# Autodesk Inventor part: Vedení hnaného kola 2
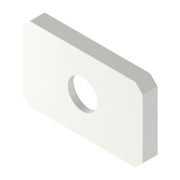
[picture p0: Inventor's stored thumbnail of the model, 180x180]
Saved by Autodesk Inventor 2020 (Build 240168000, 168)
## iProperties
Created: 2025-03
Part Number: Vedení hnaného kola 2
Material: Ocel
Document SubType Name: Modeling
Designer: doma
Density: 7.85 g/cm^3
Appearance: Ocel
Mass: 132.762 g
Surface Area: 69.1695 cm^2
Volume: 16.9123 cm^3
Author: doma
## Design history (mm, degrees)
sketch "Náčrt1"
  geometry: C1 r 37.5 at (0, 0); C2 r 17.5 at (0, 0)
  constraints: 2 centre point, 1 coincident
  dimensions: "d3" = 75 diameter of C1; "d4" = 35 diameter of C2
extrude "Vysunutí1" new body sketch "Náčrt1" distance "d7" = 8; taper "d8" = 0 deg
sketch "Náčrt2"
  geometry: L1 (-28.5, -20)-(28.5, -20); L2 (32.5, -16)-(32.5, 16); L3 (28.5, 20)-(-28.5, 20); L4 (-32.5, 16)-(-32.5, -16); L5 (-32.5, -20)-(32.5, 20); L6 (32.5, -20)-(-32.5, 20); L7 (-80.934, -49.806)-(80.934, -49.806); L8 (80.934, -49.806)-(80.934, 49.806); L9 (80.934, 49.806)-(-80.934, 49.806); L10 (-80.934, 49.806)-(-80.934, -49.806); L11 (-80.934, -49.806)-(80.934, 49.806); L12 (80.934, -49.806)-(-80.934, 49.806); L13 (-32.5, 16)-(-28.5, 20); L14 (32.5, 16)-(28.5, 20); L15 (28.5, -20)-(32.5, -16); L16 (-32.5, -16)-(-28.5, -20); 1 further point
  constraints: 32 end point, 8 point on line, 4 midpoint, 4 parallel, 2 horizontal, 2 perpendicular
  dimensions: "d9" = 65 distance of L6.end L5.end; "d10" = 40 distance of L5.end L6.start; "d13" = 4 distance of L4.start L6.end; "d14" = 4 distance of L3.end L6.end (= d13); "d15" = 4 distance of L2.end L5.end (= d13); "d16" = 4 distance of L3.start L5.end (= d15); "d17" = 4 distance of L1.end L6.start (= d13); "d18" = 4 distance of L2.start L6.start (= d17); "d19" = 4 distance of L4.end L5.start (= d13); "d20" = 4 distance of L1.start L5.start (= d19)
extrude "Vysunutí2" cut sketch "Náčrt2" distance "d11" = 8; taper "d12" = 0 deg
sketch "Náčrt3"
  geometry: C1 r 8 at (0, 0); C2 r 17.5 at (0, 0); C3 r 17.5 at (0, 0) reference; C4 r 17.5 at (0, 0) reference; 1 further point
  constraints: 2 centre point, 2 coincident, 1 concentric
  dimensions: "d21" = 16 diameter of C1
extrude "Vysunutí3" join sketch "Náčrt3" distance "d22" = 4; taper "d23" = 0 deg
fillet "Zaoblení1" dims "d24" = 0.2
chamfer "Zkosení1" distance "d25" = 1; stored, may be unused: second distance "d26" = 2, angle "d27" = 45 deg
chamfer "Zkosení2" distance "d28" = 1; stored, may be unused: second distance "d29" = 2, angle "d30" = 45 deg
node "Těleso1"
node "Referenční1"
